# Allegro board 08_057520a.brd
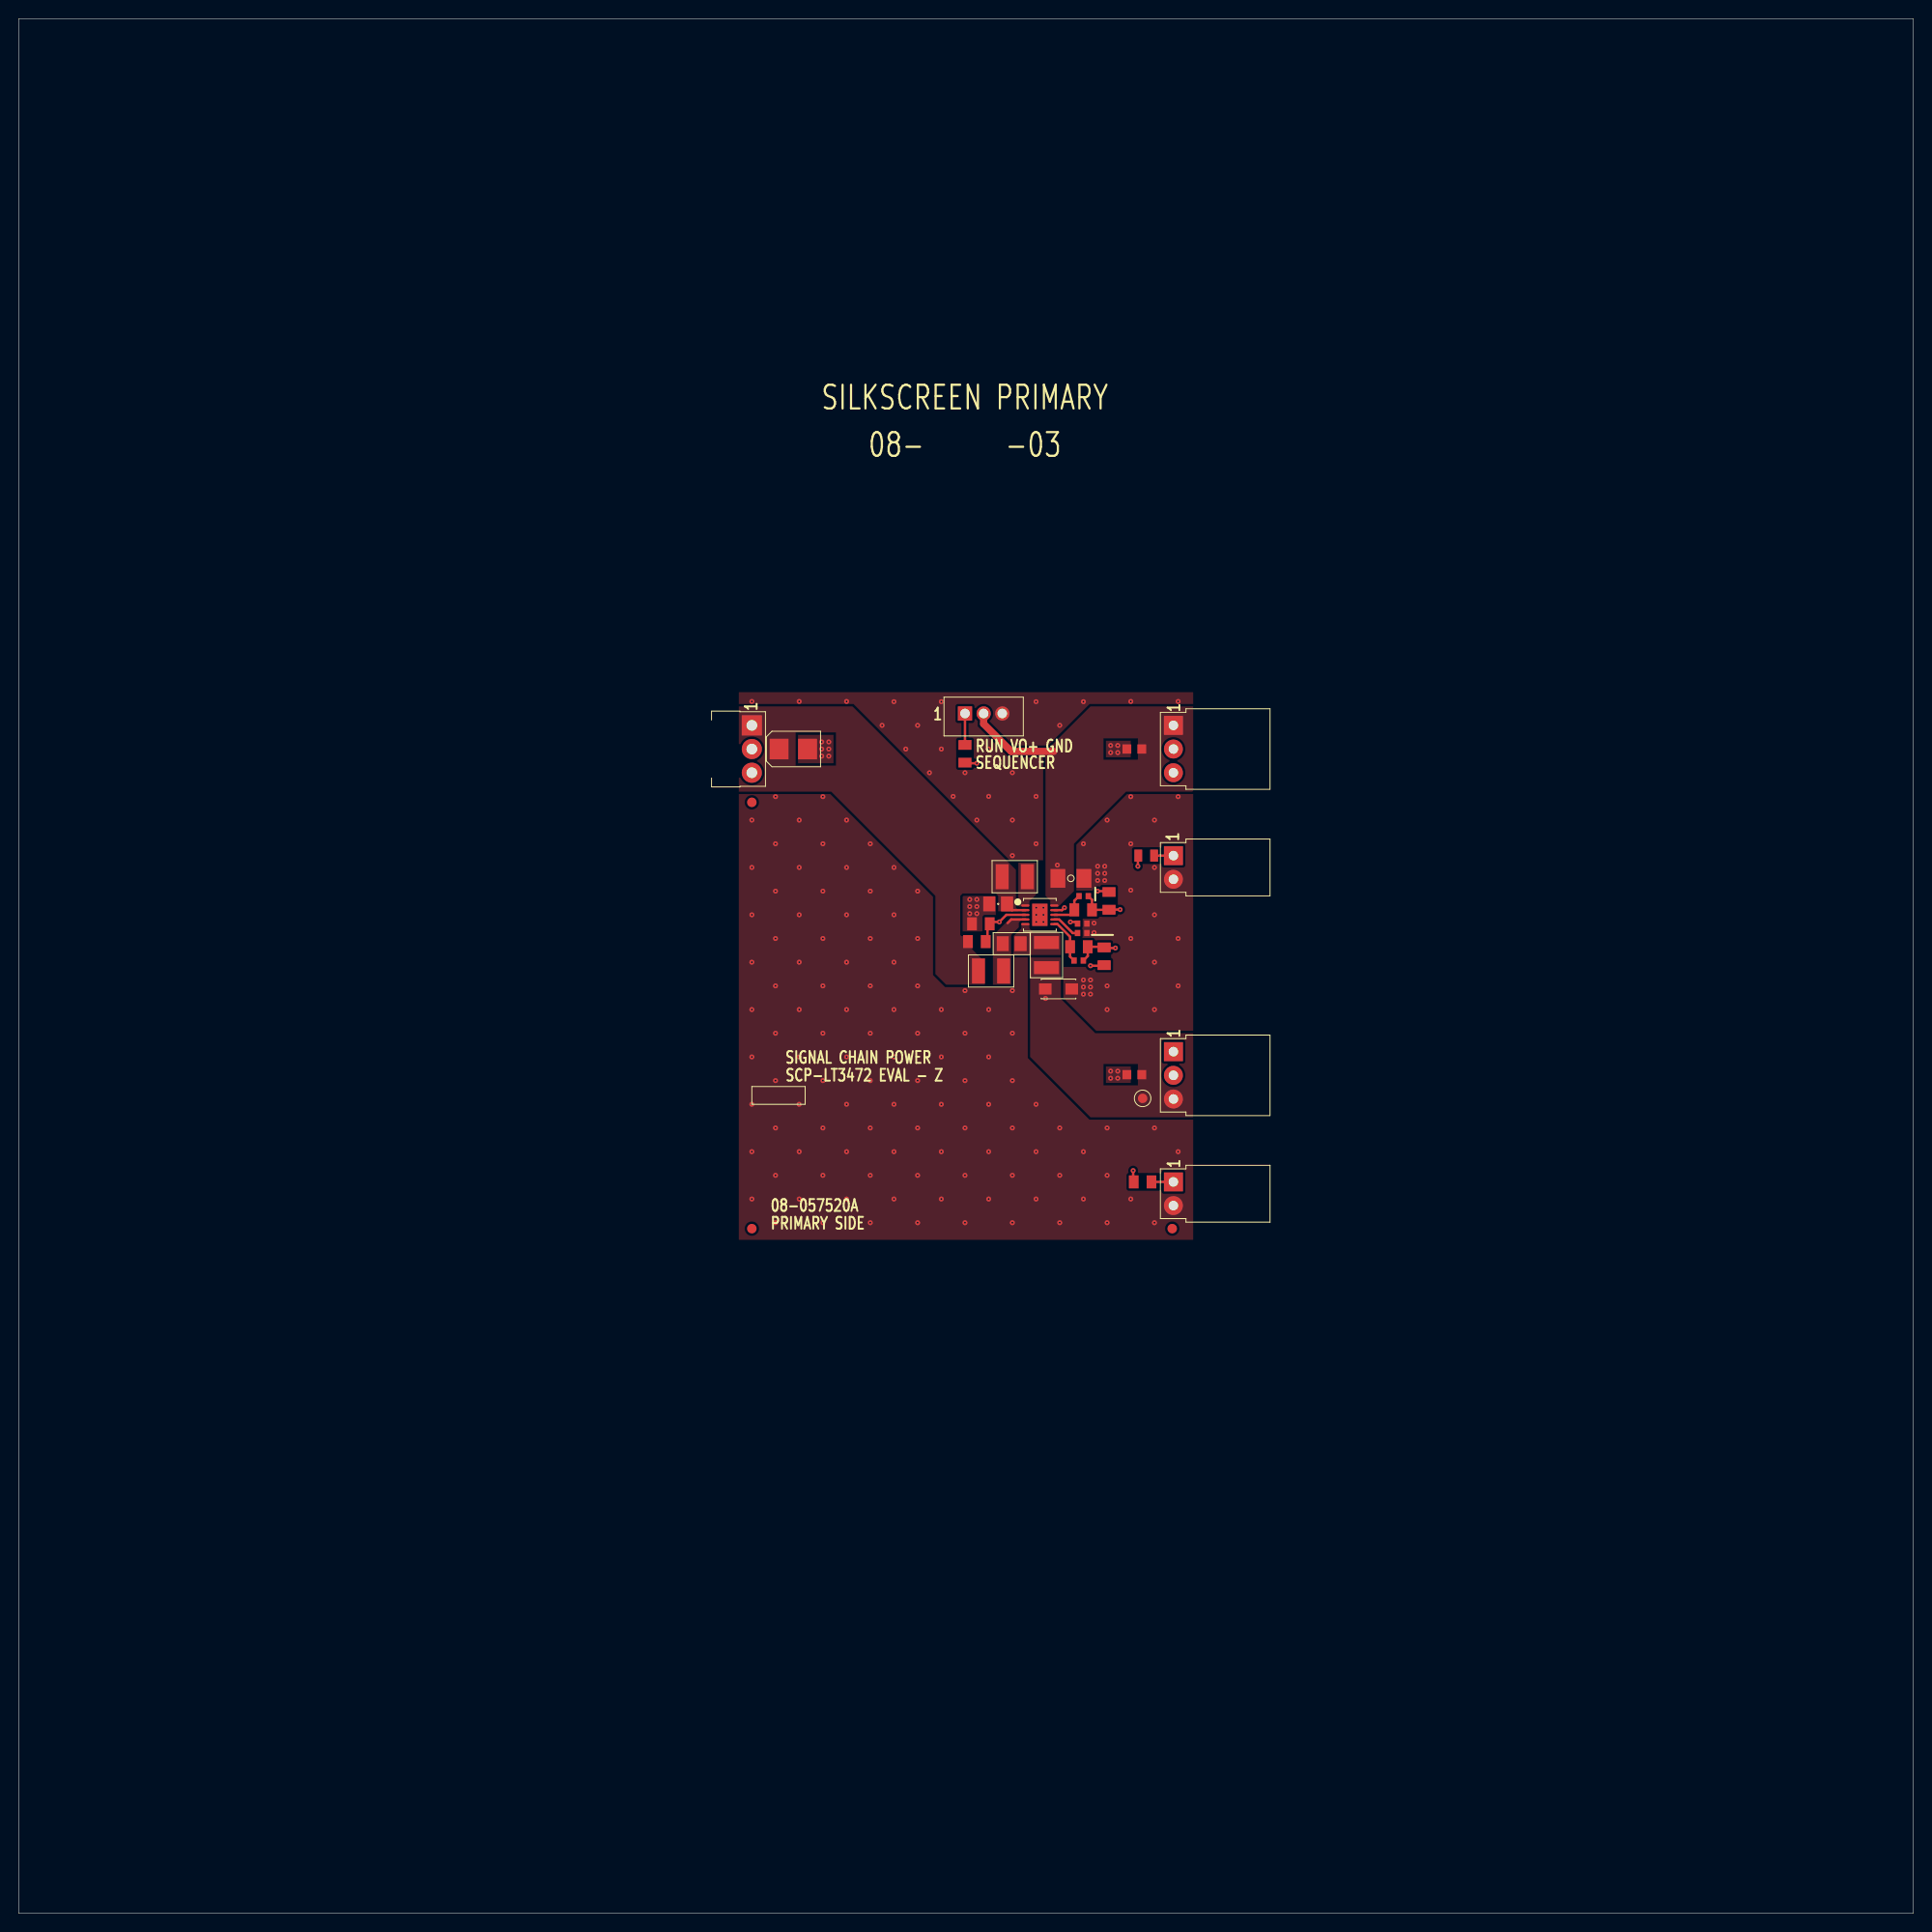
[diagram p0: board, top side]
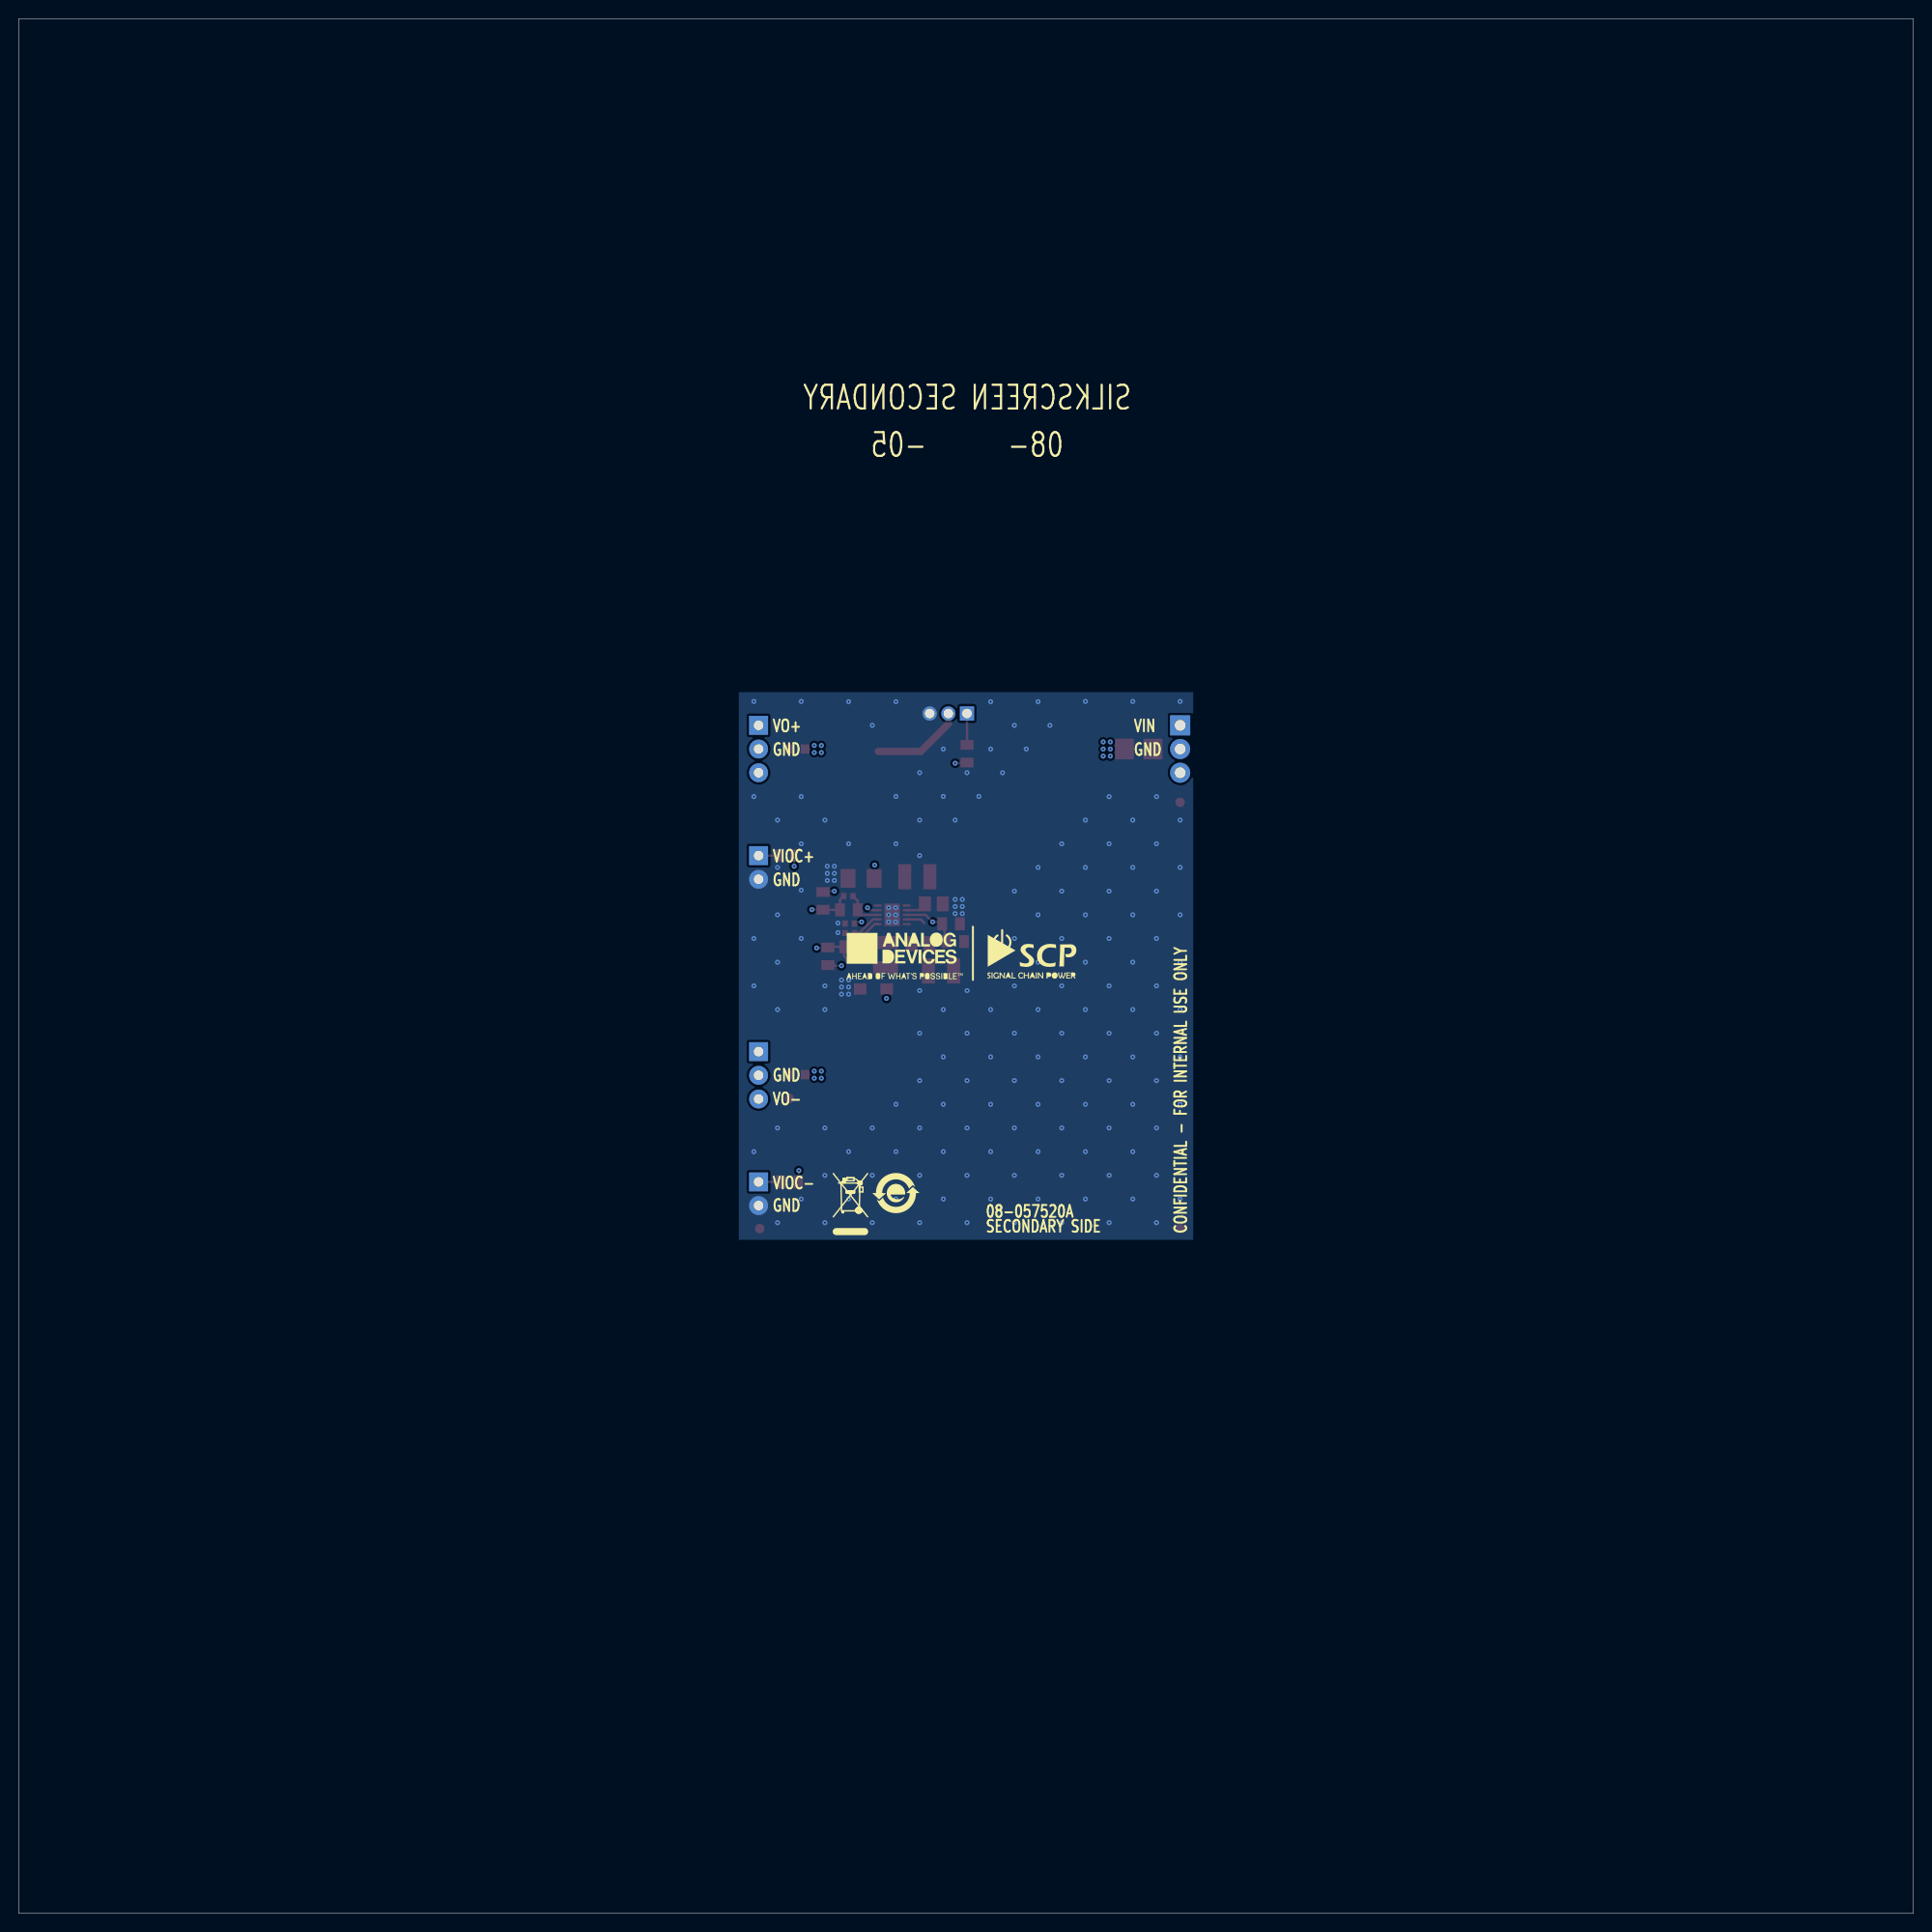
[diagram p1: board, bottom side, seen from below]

Outline 203.2 x 203.2 mm; copper layers: TOP, L2_GND, L3_SIG, BOTTOM. Coordinates in mm from the lower left corner of the outline.
Outline path: 0,203.2 203.2,203.2 203.2,0 0,0 0,203.2

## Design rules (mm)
constraint set DEFAULT: min track width 0.203

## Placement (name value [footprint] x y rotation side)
C1  1UF  [C0805H53]  106.5 103.99 0 top
C2  2.2uF  [C0805H60]  105.05 108.26 0 top
C3  2.2UF  [C1206H71-2]  111.53 99.14 180 top
C4  4.7UF  [C1206H71]  112.85 111 180 top
C5  0.22UF  [C0402]  114.07 105.13 180 top
C6  0.22UF  [C0402]  114.07 106.15 180 top
C7  10PF  [C0402]  114.22 109.1 180 top
C8  0.1UF  [C0603]  119.65 124.87 0 top
C9  0.1UF  [C0603]  119.65 89.94 0 top
C10  TBD3528  [C3528]  83.08 124.87 0 top
C11  10PF  [C0402]  113.68 102.19 0 top
INPUT  PBC03SBAN  [CNTHMHDRRA1X3L300W100H145]  78.63 127.41 270 top
L1  22UH  [L1210H67_A]  106.83 111.18 180 top
L2  47UH  [L1210H67_A]  104.29 101.07 180 top
L3  47UH  [L1210H67_A]  110.23 102.77 270 top
NOREF  -  []  209.44 65.18 0 top
NOREF#2  -  []  76.6 131.6 0 top
NOREF#3  -  []  76.6 71.6 0 top
NOREF#4  -  []  -273.05 -196.85 0 top
NOREF#5  -  []  76.6 131.6 0 top
NOREF#6  -  []  126.6 71.6 90 top
NOREF#7  -  [unnamed#2]  78.63 119.15 0 top
NOREF#8  -  []  126.6 131.6 180 top
NOREF#9  -  [unnamed#2]  123.72 73.43 0 top
NOREF#10  -  []  76.6 131.6 0 top
NOREF#11  -  [unnamed#2]  78.63 73.43 0 top
NOREF#12  -  []  158.64 239.17 0 top
NOREF#13  -  []  53.87 15.01 0 top
NOREF#14  -  []  126.6 71.6 90 top
NOREF#15  -  []  161.82 133.76 0 top
NOREF#16  -  []  41.8 -101.19 0 top
NOREF#17  -  []  -273.05 -196.85 0 top
NOREF#18  -  []  101.47 156.34 0 top
NOREF#19  -  []  76.6 131.6 270 top
NOREF#20  -  []  94.51 102.9 180 bottom
NOREF#21  -  []  108.48 102.64 180 bottom
NOREF#22  -  []  109.11 77.24 180 bottom
NOREF#23  -  []  114.19 72.8 180 bottom
OUTPUT1  PPPC031LGBN-RC  [CNHDRRA1X3H108]  123.84 92.42 270 top
OUTPUT2  PPPC031LGBN-RC  [CNHDRRA1X3H108]  123.84 127.41 270 top
P1  53253-0370  [CNTHMHDR1X3L315W144H224]  101.49 128.68 0 top
R1  100K  [R0805]  103.19 106.12 180 top
R2  324K  [R0805]  113.71 103.66 180 top
R3  549K  [R0805]  114.17 107.62 0 top
R4  0  [R0805]  102.76 104.22 180 top
R5  0  [R0805]  101.49 124.36 90 top
R6  0  [R0805]  116.94 108.59 90 top
R7  TBD0805  [R0805#2]  120.92 113.44 180 top
R8  0  [R0805]  116.41 102.64 270 top
R9  TBD0805  [R0805]  120.54 78.45 0 top
U1  LT3472EDD#PBF  [DFN10_3X3_PAD2_38X1_64]  109.52 107.09 270 top
VIOC+  PPPC021LGBN-RC  [CNTHFHDRRA1X2L220W335H108]  123.84 113.44 270 top
VIOC-  PPPC021LGBN-RC  [CNTHFHDRRA1X2L220W335H108]  123.84 78.45 270 top
VNEG  TESTPAD  [TPSMC40]  120.54 87.4 0 top

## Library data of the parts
C1 = CAP: Tolerance: 10; User Part Number: UPN; alternate symbols: (); part number: CAP_SM-1UF,50V,10,E033068,C0805H53; tolerance: 10
C2 = CAP: Tolerance: 10; User Part Number: UPN; alternate symbols: (); part number: CAP_SM-2.2UF,50V,10,E016729,C0805H60; tolerance: 10
C3 = CAP: Tolerance: 10; User Part Number: UPN; alternate symbols: (); part number: CAP_SM-2.2UF,50V,10,E034235,C1206H71-2; tolerance: 10
C4 = CAP: Tolerance: 10; User Part Number: UPN; alternate symbols: (); part number: CAP_SM-4.7UF,50V,10,E038262,C1206H71; tolerance: 10
C5 C6 = CAP: User Part Number: UPN; Tolerance: 10; alternate symbols: (); part number: CAP_SM-0.22UF,50V,10,E038241,C0402; tolerance: 10
C7 C11 = CAP: User Part Number: UPN; Tolerance: 5; alternate symbols: (); part number: CAP_SM-10PF,50V,5,E035301,C0402; tolerance: 5
C8 C9 = CAP: User Part Number: UPN; Tolerance: 10; alternate symbols: (); part number: CAP_SM-0.1UF,50V,10,E038267,C0603; tolerance: 10
C10 = CAPP: User Part Number: UPN; alternate symbols: (); part number: CAPP_SM-TBD3528,TBD3528,TBD3528,E006614,C3528
INPUT = CN3P: Tolerance: N/A; User Part Number: UPN; alternate symbols: (CNTHMHDRRA1X3L300W100H145_SCP); part number: CN3P_TH-PBC03SBAN,E034137,CNTHMHDRRA1X3L300W100H145; tolerance: N/A
L1 = IND: User Part Number: UPN; Tolerance: 10; alternate symbols: (); part number: IND_SM-22UH,10,E038545,L1210H67_A; tolerance: 10
L2 L3 = IND: User Part Number: UPN; Tolerance: 10; alternate symbols: (); part number: IND_SM-47UH,10,E038544,L1210H67_A; tolerance: 10
OUTPUT1 OUTPUT2 = CN3P: User Part Number: UPN; Tolerance: N/A; alternate symbols: (CNHDRRA1X3H108_SCP); part number: CN3P_TH-PPPC031LGBN-RC,E034111,CNHDRRA1X3H108; tolerance: N/A
P1 = CN3P: Tolerance: N/A; User Part Number: UPN; alternate symbols: (); part number: CN3P_TH-53253-0370,E033940,CNTHMHDR1X3L315W144H224; tolerance: N/A
R1 = RES: User Part Number: UPN; Tolerance: 1; alternate symbols: (R0805L); part number: RES_SM-100K,E003488,1/8W,1,R0805; tolerance: 1
R2 = RES: User Part Number: UPN; Tolerance: 0.1; alternate symbols: (); part number: RES_SM-324K,E035885,1/8W,0.1,R0805; tolerance: 0.1
R3 = RES: User Part Number: UPN; Tolerance: 0.1; alternate symbols: (); part number: RES_SM-549K,E035873,1/8W,0.1,R0805; tolerance: 0.1
R4-R6 R8 = RES: User Part Number: UPN; Tolerance: N/A; alternate symbols: (R0805L); part number: RES_SM-0,E030875,1/8W,N/A,R0805; tolerance: N/A
R7 R9 = RES: User Part Number: UPN; alternate symbols: (R0805L); part number: RES_SM-TBD0805,E004051,TBD0805,TBD0805,R0805
U1 = ADLT3472: Tolerance: N/A; User Part Number: UPN; alternate symbols: (); part number: ADLT3472_SM-LT3472EDD#PBF,E035787,DFN10_3X3_PAD2_38X1_64; tolerance: N/A
VIOC+ VIOC- = CN2P: Tolerance: N/A; User Part Number: UPN; alternate symbols: (CNTHFHDRRA1X2L220W335H108_SCP); part number: CN2P_TH-PPPC021LGBN-RC,E034113,CNTHFHDRRA1X2L220W335H108; tolerance: N/A
VNEG = NCTESTPAD: Tolerance: N/A; User Part Number: UPN; alternate symbols: (); part number: NCTESTPAD_SM-TESTPAD,E019801,TPSMC40; tolerance: N/A

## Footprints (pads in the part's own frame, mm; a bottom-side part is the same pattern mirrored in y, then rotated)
C0402
  rect 0.584x0.66 smd: 1(-0.5,0) 2(0.5,0)
C0603
  rect 0.94x0.991 smd: 1(-0.8,0) 2(0.8,0)
C0805H53
  rect 1.295x1.6 smd: 1(-0.953,0) 2(0.953,0)
C0805H60
  rect 1.295x1.6 smd: 1(-0.953,0) 2(0.953,0)
C1206H71
  rect 1.6x2.007 smd: 1(-1.397,0) 2(1.397,0)
C1206H71-2
  rect 1.346x1.194 smd: 1(-1.423,0) 2(1.423,0)
C3528
  rect 2.032x2.21 smd: N(1.524,0) P(-1.524,0)
CNHDRRA1X3H108
  rect 2.032x2.032 hole 1.016: 1(0,0)
  round 2.032 hole 1.016: 2(2.54,0) 3(5.08,0)
CNTHFHDRRA1X2L220W335H108
  rect 2.032x2.032 hole 1.016: 1(0,0)
  round 2.032 hole 1.016: 2(2.54,0)
CNTHMHDR1X3L315W144H224
  rect 1.524x1.524 hole 1.016: 1(0,0)
  round 1.524 hole 1.016: 2(2,0) 3(4,0)
CNTHMHDRRA1X3L300W100H145
  rect 2.159x2.159 hole 1.143: 1(0,0)
  round 2.159 hole 1.143: 2(2.54,0) 3(5.08,0)
DFN10_3X3_PAD2_38X1_64
  oval 0.254x0.889 smd: 1(-1,-1.555) 2(-0.5,-1.555) 3(0,-1.555) 4(0.5,-1.555) 5(1,-1.555) 6(1,1.555) 7(0.5,1.555) 8(0,1.555) 9(-0.5,1.555) 10(-1,1.555)
  rect 2.388x1.651 smd: PAD(0,0)
L1210H67_A
  rect 1.397x2.692 smd: 1(-1.35,0) 2(1.35,0)
R0805
  rect 1.041x1.397 smd: 1(-0.95,0) 2(0.95,0)
R0805#2
  rect 0.838x1.295 smd: 1(-0.85,0) 2(0.85,0)
TPSMC40
  round 1.016 smd: 1(0,0)
unnamed#2
  round 1.016 smd: (0,0)

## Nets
GND: C2.1 C3.1 C4.1 C5.1 C6.1 C8.1 C9.1 C10.N(N2) INPUT.2 OUTPUT1.2 OUTPUT2.2 P1.3(N3) R1.2(N2) U1.PAD VIOC+.2(N2) VIOC-.2(N2)
UNNAMED_2_ADLT3472_I34_SSN: C5.2(N2) U1.7
UNNAMED_2_ADLT3472_I34_SSP: C6.2(N2) U1.9
UNNAMED_2_ADLT3472_I34_SWP: L1.1 U1.1
UNNAMED_2_CAP_I2_N2: C2.2(N2) C10.P INPUT.1 L1.2(N2) L2.2(N2) R4.2(N2) U1.2
UNNAMED_2_CAP_I6_N1: C1.1 L2.1 U1.4
UNNAMED_2_CAP_I6_N2: C1.2(N2) L3.1 U1.5
UNNAMED_2_CAP_I10_N1: C11.1 R2.2(N2) U1.6
UNNAMED_2_CAP_I10_N2: C11.2(N2) R2.1 R8.1 R9.1
UNNAMED_2_CAP_I20_N1: C7.1 R3.2(N2) R6.1 R7.2(N2)
UNNAMED_2_CAP_I20_N2: C7.2(N2) R3.1 U1.8
UNNAMED_2_CN2P_I53_N1: R9.2(N2) VIOC-.1
UNNAMED_2_CN2P_I58_N1: R7.1 VIOC+.1
UNNAMED_2_CN3P_I30_N1: P1.1 R5.2(N2)
UNNAMED_2_RES_I25_N1: R1.1 R4.1 R5.1 U1.3
VNEG: C3.2(N2) C9.2(N2) L3.2(N2) OUTPUT1.3(N3) R8.2(N2) VNEG.1(N1)
VPOS: C4.2(N2) C8.2(N2) OUTPUT2.1 P1.2 R6.2(N2) U1.10(VPOS)

Pads without a net: INPUT 3; OUTPUT1 1; OUTPUT2 3

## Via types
v1: diameter 0.533, hole 0.203, TOP to BOTTOM, 202 vias

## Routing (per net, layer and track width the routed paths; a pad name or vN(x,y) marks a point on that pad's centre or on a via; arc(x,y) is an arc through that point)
GND:
  vias: v1(78.63,129.97) v1(78.63,117.25) v1(78.63,112.17) v1(78.63,107.09) v1(78.63,102.01) v1(78.63,96.93) v1(78.63,91.85) v1(78.63,86.77) v1(78.63,81.69) v1(78.63,76.61) v1(81.17,119.76) v1(81.17,114.71) v1(81.17,109.63) v1(81.17,104.55) v1(81.17,99.47) v1(81.17,94.39) v1(81.17,89.31) v1(81.17,84.23) v1(81.17,79.15) v1(81.17,74.07) v1(83.71,129.97) v1(83.71,117.25) v1(83.71,112.17) v1(83.71,107.09) v1(83.71,102.01) v1(83.71,96.93) v1(83.71,91.85) v1(83.71,86.77) v1(83.71,81.69) v1(83.71,76.61) v1(86.13,125.63) v1(86.13,124.87) v1(86.13,124.11) v1(86.25,119.76) v1(86.25,114.71) v1(86.25,109.63) v1(86.25,104.55) v1(86.25,99.47) v1(86.25,94.39) v1(86.25,89.31) v1(86.25,84.23) v1(86.25,79.15) v1(86.25,74.07) v1(86.89,125.63) v1(86.89,124.87) v1(86.89,124.11) v1(88.79,129.97) v1(88.79,117.25) v1(88.79,112.17) v1(88.79,107.09) v1(88.79,102.01) v1(88.79,96.93) v1(88.79,91.85) v1(88.79,86.77) v1(88.79,81.69) v1(88.79,76.61) v1(91.33,114.71) v1(91.33,109.63) v1(91.33,104.55) v1(91.33,99.47) v1(91.33,94.39) v1(91.33,89.31) v1(91.33,84.23) v1(91.33,79.15) v1(91.33,74.07) v1(92.6,127.41) v1(93.87,129.95) v1(93.87,112.17) v1(93.87,107.09) v1(93.87,102.01) v1(93.87,96.93) v1(93.87,91.85) v1(93.87,86.77) v1(93.87,81.69) v1(93.87,76.61) v1(95.14,124.87) v1(96.41,127.41) v1(96.41,109.63) v1(96.41,104.55) v1(96.41,99.47) v1(96.41,94.39) v1(96.41,89.31) v1(96.41,84.23) v1(96.41,79.15) v1(96.41,74.07) v1(97.68,122.33) v1(98.95,129.95) v1(98.95,124.87) v1(98.95,96.93) v1(98.95,91.85) v1(98.95,86.77) v1(98.95,81.69) v1(98.95,76.61) v1(100.22,119.79) v1(101.49,122.33) v1(101.49,98.96) v1(101.49,94.39) v1(101.49,89.31) v1(101.49,84.23) v1(101.49,79.15) v1(101.49,74.07) v1(102,108.74) v1(102,107.98) v1(102,107.22) v1(102.76,117.25) v1(102.76,108.74) v1(102.76,107.98) v1(102.76,107.22) v1(104.03,124.87) v1(104.03,119.79) v1(104.03,96.93) v1(104.03,91.85) v1(104.03,86.77) v1(104.03,81.69) v1(104.03,76.61) v1(106.57,122.33) v1(106.57,117.25) v1(106.57,113.44) v1(106.57,98.96) v1(106.57,94.39) v1(106.57,89.31) v1(106.57,84.23) v1(106.57,79.15) v1(106.57,74.07) v1(109.11,129.95) v1(109.11,119.79) v1(109.11,114.71) v1(109.14,107.85) v1(109.14,107.09) v1(109.14,106.33) v1(109.11,86.77) v1(109.11,81.69) v1(109.11,76.61) v1(109.9,107.85) v1(109.9,107.09) v1(109.9,106.33) v1(111.65,127.41) v1(111.65,84.23) v1(111.65,79.15) v1(111.65,74.07) v1(114.19,129.95) v1(114.19,114.71) v1(114.19,100.1) v1(114.19,99.34) v1(114.19,98.58) v1(114.19,81.69) v1(114.19,76.61) v1(114.95,100.1) v1(114.95,99.34) v1(114.95,98.58) v1(115.34,106.2) v1(115.34,105.18) v1(115.72,112.3) v1(115.72,111.53) v1(115.72,110.77) v1(116.48,112.3) v1(116.48,111.53) v1(116.48,110.77) v1(116.73,117.25) v1(116.73,99.47) v1(116.73,96.93) v1(116.73,84.23) v1(116.73,79.15) v1(116.73,74.07) v1(117.11,125.25) v1(117.11,124.49) v1(117.11,90.32) v1(117.11,89.56) v1(117.88,125.25) v1(117.88,124.49) v1(117.88,90.32) v1(117.88,89.56) v1(119.27,129.97) v1(119.27,119.76) v1(119.27,114.71) v1(119.27,109.73) v1(119.27,104.55) v1(119.27,76.61) v1(121.81,117.25) v1(121.81,112.17) v1(121.81,107.09) v1(121.81,102.01) v1(121.81,96.93) v1(121.81,84.23) v1(121.81,74.07) v1(124.35,129.97) v1(124.35,119.76) v1(124.35,104.55) v1(124.35,99.47) v1(124.35,81.69)
UNNAMED_2_ADLT3472_I34_SSN: length 3.1
  TOP w0.254: U1.7 111.59,106.59 113.05,105.13 C5.2
UNNAMED_2_ADLT3472_I34_SSP: length 3.8
  TOP w0.254: U1.9 111.9,107.59 v1(112.16,107.85) ; C6.2 113.39,106.33 v1(112.8,106.33)
  L3_SIG w0.254: v1(112.16,107.85) 112.8,107.22 v1(112.8,106.33)
UNNAMED_2_CAP_I2_N2: length 2.3
  TOP w0.254: C2.2 106,108.13 106.54,107.59 U1.2
UNNAMED_2_CAP_I6_N1: length 2.1
  TOP w0.254: U1.4 106.45,106.59 106.06,106.2
UNNAMED_2_CAP_I10_N1: length 5
  TOP w0.254: C11.1 112.76,102.61 R2.2 112.76,104.74 111.41,106.09 U1.6
UNNAMED_2_CAP_I10_N2: length 30.6
  TOP w0.254: C11.2 114.66,102.66 R2.1 116.35,103.66 R8.1 116.48,103.53 v1(117.62,103.53) ; R9.1 119.53,78.51 v1(119.53,79.66)
  L3_SIG w0.254: v1(117.62,103.53) 119.53,101.63 v1(119.53,79.66)
UNNAMED_2_CAP_I20_N1: length 11.3
  TOP w0.254: R7.2 120.03,113.4 v1(120.03,112.3) ; v1(118.13,107.65) 116.95,107.65 R6.1 116.92,107.62 R3.2 115.12,108.7 C7.1
  L3_SIG w0.254: v1(118.13,107.65) 120.03,109.55 v1(120.03,112.3)
UNNAMED_2_CAP_I20_N2: length 4.1
  TOP w0.254: U1.8 112.8,107.09 113.22,107.51 R3.1 113.22,108.59 C7.2
UNNAMED_2_CN2P_I53_N1: length 2.4
  TOP w0.254: R9.2 VIOC-.1
UNNAMED_2_CN2P_I58_N1: length 2.1
  TOP w0.254: R7.1 VIOC+.1
UNNAMED_2_CN3P_I30_N1: length 3.4
  TOP w0.254: R5.2 P1.1
UNNAMED_2_RES_I25_N1: length 25.6
  TOP w0.254: v1(102.76,123.34) 101.56,123.34 R5.1 ; R4.1 103.91,104.41 103.91,105.88 R1.1 104.35,106.33 v1(105.17,106.33) 105.93,107.09 U1.3
  L3_SIG w0.254: v1(105.17,106.33) 105.17,120.93 v1(102.76,123.34)
VNEG: length 7.8
  TOP w0.254: v1(114.95,101.63) 116.35,101.63 R8.2
  L3_SIG w0.254: v1(110.13,98.12) 113.63,101.63 v1(114.95,101.63)
VPOS: length 16.6
  TOP w0.254: R6.2 116.84,109.63 v1(115.72,109.63)
  TOP w0.762: 111.02,124.61 106.45,124.61 103.49,127.57 P1.2
  L3_SIG w0.254: v1(111.4,112.42) 112.92,112.42 v1(115.72,109.63)

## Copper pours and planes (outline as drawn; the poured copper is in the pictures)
GND on TOP: 83.59,123.34 87.4,123.34 87.4,126.39 83.59,126.39
GND on TOP: 119.27,89.05 116.61,89.05 116.61,90.83 119.27,90.83
GND on TOP: 116.61,123.98 116.61,125.76 119.27,125.76 119.27,123.98
GND on TOP: 77.24,130.96 125.96,130.96 125.96,72.24 77.24,72.24 77.24,120.04 80.92,120.04 80.92,123.09 83.71,123.09 83.71,125.99 80.92,125.99 80.92,129.69 77.24,129.69 ; 13 cut-outs
GND on BOTTOM: 77.24,130.96 125.96,130.96 125.96,72.24 77.24,72.24 ; 6 cut-outs
GND on L2_GND: 77.24,130.96 125.96,130.96 125.96,129.7 114.85,129.7 109.87,124.72 109.87,110.26 110.13,110.26 110.13,124.61 114.95,129.44 125.96,129.44 125.96,120.3 118.76,120.3 113.18,114.71 113.18,113.44 116.1,113.44 116.1,113.69 113.43,113.69 113.43,114.61 118.87,120.04 125.96,120.04 125.96,94.64 115.59,94.64 113.18,97.06 115.21,97.06 115.21,97.31 112.54,97.31 115.46,94.39 125.96,94.39 125.96,85.37 114.95,85.37 108.48,91.85 108.48,102.77 108.22,102.77 108.22,91.75 114.85,85.12 125.96,85.12 125.96,72.24 77.24,72.24 77.24,120.04 87.04,120.04 98.06,109.02 98.06,106.83 98.32,106.83 98.32,109.12 87.14,120.3 77.24,120.3 77.24,129.44 89.43,129.44 106.95,111.91 106.95,110.26 107.21,110.26 107.21,112.02 89.53,129.69 77.24,129.69
GND on L3_SIG: 77.24,130.96 125.96,130.96 125.96,72.24 77.24,72.24 ; 6 cut-outs
UNNAMED_2_ADLT3472_I34_SWP on TOP: 108.32,107.98 107.33,107.98 107.21,108.1 107.21,112.68 109.11,112.68 109.11,109.25 108.4,108.54 108.4,108.05
UNNAMED_2_CAP_I2_N2 on TOP: 105.05,107.47 105.05,109.12 104.79,109.37 101.24,109.37 100.98,109.12 100.98,104.93 101.11,104.8 102.25,104.8 102.25,103.41 103.63,102.03 103.63,99.6 99.46,99.6 98.32,100.74 98.32,109.12 87.14,120.3 77.24,120.3 77.24,129.44 89.43,129.44 106.95,111.91 106.95,107.85 107.21,107.6 107.21,107.47
UNNAMED_2_CAP_I6_N1 on TOP: 106.45,104.93 106.45,99.6 104.49,99.6 104.49,104.88 106.32,106.71 107.98,106.71 107.98,106.47 107.49,106.47 107.26,106.25 107.26,105.75
UNNAMED_2_CAP_I6_N2 on TOP: 107.59,106.2 108.32,106.2 108.4,106.12 108.4,105.64 108.73,105.31 111.4,105.31 111.78,104.93 111.78,102.77 106.7,102.77 106.7,104.8 107.54,105.64 107.54,106.15
VNEG on TOP: 125.96,85.37 114.95,85.37 108.48,91.85 108.48,102.52 111.78,102.52 111.78,98.07 115.46,94.39 125.96,94.39 ; 1 cut-out
VPOS on TOP: 110.13,123.98 109.49,124.61 109.87,125 110.51,125 114.95,129.44 125.96,129.44 125.96,120.39 125.88,120.3 118.76,120.3 113.18,114.71 113.18,109.63 111.53,107.98 110.76,107.98 110.64,108.1 110.64,108.61 110.13,109.12 ; 1 cut-out

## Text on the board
Ref Des/Silkscreen Bottom: VIN | GND | 08-057520A | SECONDARY SIDE | VO+ | VIOC+ | VO- | VIOC- | CONFIDENTIAL - FOR INTERNAL USE ONLY
User.Comments: WITH LEAD-FREE AND RoHS PCB ASSEMBLY STANDARDS (EU RoHS | DIRECTIVE 2002/95/EC). | 4.    RoHS COMPLIANCE: ASSEMBLY VENDOR SHOULD ASSURE COMPLIANCE
Ref Des/Silkscreen Top: 08-057520A | PRIMARY SIDE | RUN VO+ GND | SEQUENCER | SIGNAL CHAIN POWER | SCP-LT3472 EVAL - Z
DIMENSION: REF
User.15: DIA MAX
User.17: L2 GND | 08-      -07
User.18: L3 SIG | 08-      -08
User.45: FIGURE | SIZE | 8.0 | 40.0 | 45.0 | PLATED | FINISHED HOLES IN MILS | ALL UNITS ARE IN MILS | QTY | 202 | 13 | 3 | TOLERANCE/NOTES
